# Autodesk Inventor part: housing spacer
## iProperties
Created: 2006-04
Part Number: housing spacer
Document SubType Name: Modeling
Designer: Калинин
Author: Калинин
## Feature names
1. Выдавливание1 [Extrusion]
2. Отверстие1 [Hole]
3. Сопряжение1 [Fillet]
4. Сопряжение2 [Fillet]
5. Фаска1 [Chamfer]
